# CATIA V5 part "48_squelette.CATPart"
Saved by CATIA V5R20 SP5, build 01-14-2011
Part number: 48_squelette
Publications: "Plan yz", "Point.1", "Point.5", "Point.4", "Plan.5", "Plan.7", "Plan.8", "Point.7", "Plan.9"
Bounding box of the stored display mesh (mm): x 0 to 0, y 155.362 to 169.612, z -122.5 to -122.5
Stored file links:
  C:\Documents and Settings\anizard\Bureau\13\48_squelette.CATPart
  C:\Documents and Settings\anizard\Bureau\13\anizard.CATProduct
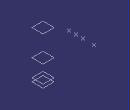
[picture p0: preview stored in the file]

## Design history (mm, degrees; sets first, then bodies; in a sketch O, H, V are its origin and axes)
Set1
  Point1: linked copy from another document
  Plane1: linked copy from another document
Body1 (main body)
  Point2: (0, 15, 0), relative to Point1
  Point3: (0, 19, 0), relative to Point1
  Point4: (0, 29.25, 0), relative to Point1
  Plane2: type Offset, RefPlane Plane1, Offset 31, reversed
  Plane3: type Offset, RefPlane Plane2, Offset 2, reversed
  Plane4: type Offset, RefPlane Plane1, Offset 6, reversed
  Point5: (0, 23, 0), relative to Point1
  Plane5: type Offset, RefPlane Plane2, Offset 10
